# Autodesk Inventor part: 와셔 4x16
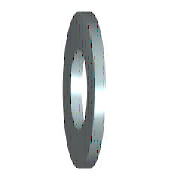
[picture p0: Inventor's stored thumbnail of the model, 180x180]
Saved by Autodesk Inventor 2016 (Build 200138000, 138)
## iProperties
IsCustomPart: 1
Created: 2012-02
Part Number: 와셔 4x16
Material: 강철, 연강
Description: 미터법 평면 와셔
Document SubType Name: Modeling
Standard: ANSI B18.22M
Designer: mduedu
Standard Revision: 1999
Standards Organization: ANSI
Language: ko-KR
Size Designation: 4 W
Categories: <MemberInstance><Categories><Category DisplayName="조임쇠" InternalName="e4da775c-781d-43d5-af7c-5136215cf5a6" Mnemonic="FSTN"><Category DisplayName="와셔" InternalN
Density: 1 g/cm^3
Appearance: 파란색 - 벽 페인트 - 광택
Author: mduedu
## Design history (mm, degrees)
sketch "스케치"
  geometry: C1 r 8 at (0, 0); C2 r 2.35 at (0, 0); 1 further point
  constraints: 2 centre point, 2 coincident
  dimensions: "d0" = 4.7 diameter of C2 (= SD1); "d1" = 16 diameter of C1 (= SD2)
extrude "본체" new body sketch "스케치" distance "d2" = 2.3 (= SD); taper "d3" = 0 deg
workaxis "Work Axis1"
workplane "Work Plane1"
body "Solid1"
other parameters: "SD1" = 4.7 [user parameter; used in 1 equation term], "SD2" = 16 [user parameter; used in 1 equation term], "SD" = 2.3 [user parameter; used in 1 equation term], "d4" = 0, "d5" = 0, "d6" = 0, "d7" = 0, "NND" = 4 [user parameter]
